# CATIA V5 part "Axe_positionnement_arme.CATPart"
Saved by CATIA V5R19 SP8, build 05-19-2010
Part number: Axe_positionnement_arme
Bounding box of the stored display mesh (mm): x -80.004 to 84.435, y -157.54 to -142.957, z 1306.37 to 1320.677
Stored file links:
  G:\EU_thinkMotion\CFAO_2010\MMS_groupe2\MMS_groupe2\OK\nrosalie\nrosalie_cfao_support_d_arme_legere_final\Axe_positionnement_arme.CATPart
  G:\EU_thinkMotion\CFAO_2010\MMS_groupe2\MMS_groupe2\OK\nrosalie\nrosalie_cfao_support_d_arme_legere_final\nrosalie_Support_d_arme_legere.CATProduct
  C:\Espace travail\Cours 2A MMS\CFAO\Projet CFAO\Modele CAO\8-01-2010\Symmetry of Bras.CATPart
  G:\EU_thinkMotion\CFAO_2010\MMS_groupe2\MMS_groupe2\OK\nrosalie\nrosalie_cfao_support_d_arme_legere_final\Bras.CATPart
  G:\EU_thinkMotion\CFAO_2010\MMS_groupe2\MMS_groupe2\OK\nrosalie\nrosalie_cfao_support_d_arme_legere_final\Squelette_Systeme_de_visee.CATPart
  G:\EU_thinkMotion\CFAO_2010\MMS_groupe2\MMS_groupe2\OK\nrosalie\nrosalie_cfao_support_d_arme_legere_final\Squelette_bras.CATPart
  G:\EU_thinkMotion\CFAO_2010\MMS_groupe2\MMS_groupe2\OK\nrosalie\nrosalie_cfao_support_d_arme_legere_final\Axe_pivot_en_site.CATPart
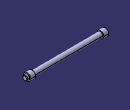
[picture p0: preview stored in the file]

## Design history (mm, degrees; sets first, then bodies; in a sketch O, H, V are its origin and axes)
Set1
  Sketch1 on yz-plane, origin (0, 0, 0), H (0, 1, 0), V (0, 0, 1)
    circle A1 centre (-150.3537, 1313.5235) radius 5
    reference projected circle E1 centre (-150.3537, 1313.5235) radius 5 from edge of DatumCurve1
    coincidence: E1 A1
Set2
  Point1: linked copy from another document
  DatumSurface1: linked copy from another document
  DatumCurve1: linked copy from another document
  DatumSurface2: linked copy from another document
Set3
  Plane1: type Offset, RefPlane DatumSurface2, Offset 0
Body1 (main body)
  Plane2: type Offset, RefPlane DatumSurface1, Offset 0
  Pad1: profile Sketch1, direction (1, 0, 0), up to Plane2, opposite side up to Plane1, offset 15
  Sketch2 on Plane2, origin (-69.8346, 0.0002, 0), H (0.0012, 1, 0), V (0, 0, 1)
    construction circle A1 centre (-150.162, 1313.5266) radius 0
    point P1 (-150.162, 1313.5266)
    line L1 (-150.162, 1313.5266) -> (-150.162, 1313.5266)
    point P2 (-150.162, 1313.5266)
    point P3 (-150.162, 1313.5266)
    line L2 (-150.162, 1313.5266) -> (-150.162, 1313.5266)
    point P4 (-150.162, 1313.5266)
    line L3 (-150.162, 1313.5266) -> (-150.162, 1313.5266)
    point P5 (-150.162, 1313.5266)
    line L4 (-150.162, 1313.5266) -> (-150.162, 1313.5266)
    point P6 (-150.162, 1313.5266)
    line L5 (-150.162, 1313.5266) -> (-150.162, 1313.5266)
    point P7 (-150.162, 1313.5266)
    line L6 (-150.162, 1313.5266) -> (-150.162, 1313.5266)
    construction line L7 (-150.162, 1308.1112) -> (-150.162, 1331.6247)
    construction line L8 (-59.6548, 1313.5266) -> (-323.4321, 1313.5266)
    axis line L9 (-150.162, 1313.5266) -> (-198.4501, 1397.1642)
    reference projected circle E1 centre (-150.162, 1313.5266) radius 5 from edge [face of Pad1 from Sketch1.A1 | start face of Pad1]
    circle A2 centre (-150.162, 1313.5266) radius 7.1921
    reference projected circle E2 centre (-150.354, 1313.5235) radius 5 from edge [end face of Pad1 | face of Pad1 from Sketch1.A1]
    angle L9 L8 = 60
    distance E2 A2 = 2
    coincidence: P2 A1, P3 A1, P4 A1, P5 A1, P6 A1, P7 A1, L7 P1, L8 P1, P4 L8, L9 P3, P7 L8
    vertical: L7 V
    horizontal: L8 H, L4 H
    symmetry: L1 L4 L8
    concentricity: A1 E1, A2 P1
  Pad2: profile Sketch2, direction (-1, 0.0012, 0), length 10
  Pad3: profile Sketch2, direction (1, -0.0012, 0), up to Plane1, opposite side up to start face of Pad1, offset -5
  Chamfer1: length 1, angle 45, on edge [face of Pad1 from Sketch1.A1 | start face of Pad1]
